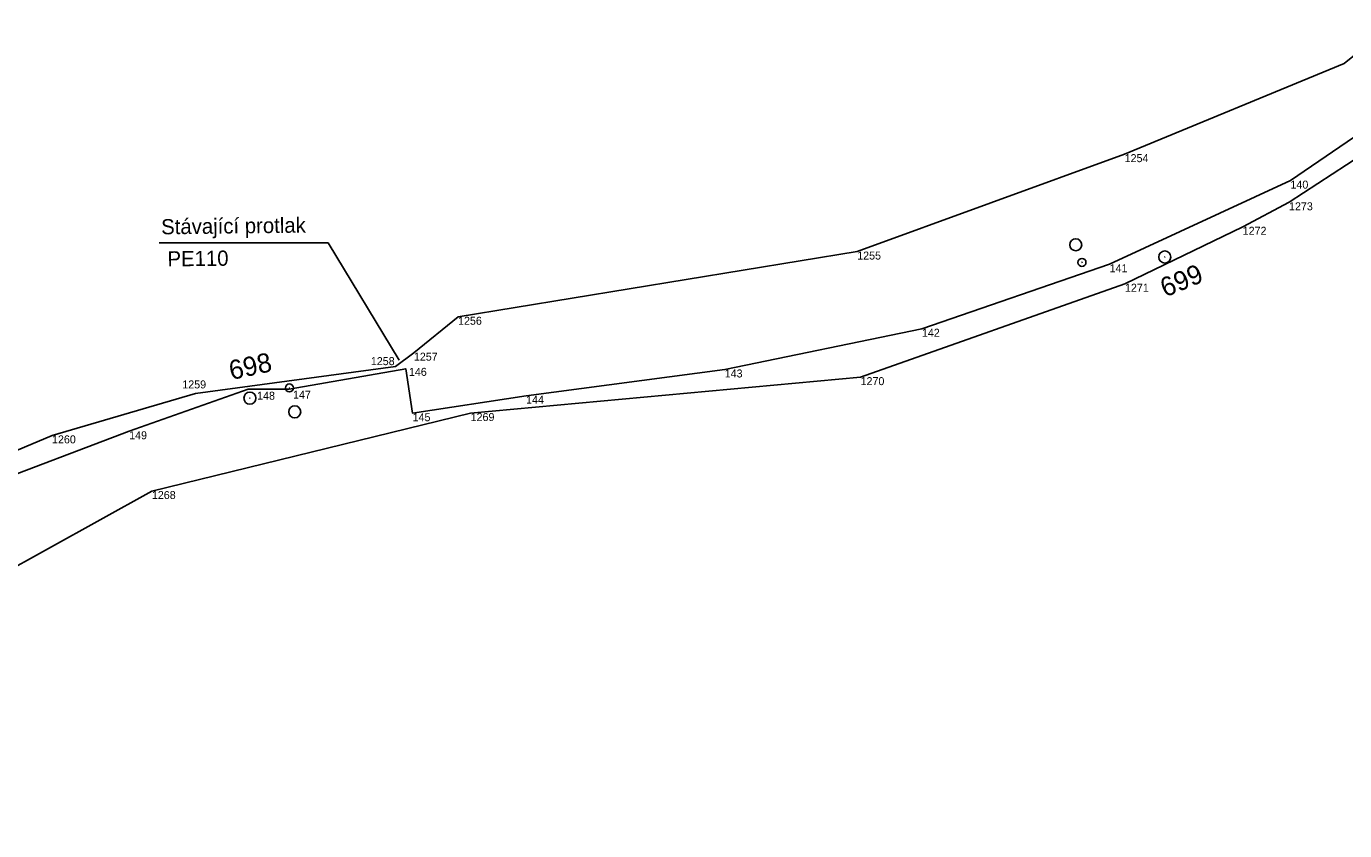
# Model space of a CAD drawing. Extents: x -679938 to -678300, y -1007495 to -1006487.
# Drawn here: x -679693.1 to -679528.4, y -1007298 to -1007197.5 of the extents above; entities that cross this region are included whole.
import ezdxf

# ---------------------------------------------------------------- set-up
doc = ezdxf.new("R2010")
doc.units = 0
for name, color, linetype in [('SSZT nové - lomové body', 7, 'Continuous'), ('SSZT_nové', 7, 'Continuous'), ('Stávající ŽBP', 7, 'Continuous'), ('SŽDC', 7, 'Continuous'), ('SŽDC - body', 7, 'Continuous'), ('Vrstva 7', 7, 'Continuous')]:
    doc.layers.add(name, color=color, linetype=linetype)

msp = doc.modelspace()

# ---------------------------------------------------------------- linework, layer by layer
at = {"layer": 'SSZT nové - lomové body'}
for p, q in [((-679535.13, -1007216.77), (-679535.13, -1007216.77)), ((-679557.73, -1007227.22), (-679557.73, -1007227.22)), ((-679581.18, -1007235.29), (-679581.18, -1007235.29)), ((-679645.68, -1007240.3), (-679645.68, -1007240.3)), ((-679605.83, -1007240.38), (-679605.83, -1007240.38)), ((-679665.36, -1007242.83), (-679665.36, -1007242.83)), ((-679660.24, -1007242.83), (-679660.24, -1007242.83)), ((-679630.65, -1007243.66), (-679630.65, -1007243.66)), ((-679644.83, -1007245.85), (-679644.83, -1007245.85)), ((-679680.25, -1007248.11), (-679680.25, -1007248.11))]:
    msp.add_line(p, q, dxfattribs=at)
at = {"layer": 'SSZT_nové'}
for q in [(-679676.5, -1007224.54), (-679646.52, -1007239.21)]:
    msp.add_line((-679655.39, -1007224.54), q, dxfattribs=at)
msp.add_lwpolyline([(-679506.94, -1007197.49), (-679535.13, -1007216.77), (-679557.73, -1007227.22), (-679581.18, -1007235.29), (-679605.83, -1007240.38), (-679630.65, -1007243.66), (-679644.83, -1007245.85), (-679645.68, -1007240.3), (-679660.24, -1007242.83), (-679665.36, -1007242.83), (-679680.25, -1007248.11), (-679698.48, -1007255.03), (-679713.76, -1007261.59), (-679729.9, -1007269.39), (-679734.01, -1007269.32), (-679749.53, -1007277.73), (-679746.78, -1007283.82), (-679755.45, -1007290.57), (-679757.54, -1007290.05), (-679765.84, -1007293.65), (-679771.62, -1007298.04)], dxfattribs=at)
at = {"layer": 'Stávající ŽBP'}
for p, q in [((-679550.89, -1007226.34), (-679550.8, -1007226.3)), ((-679665.21, -1007243.97), (-679665.11, -1007243.95))]:
    msp.add_line(p, q, dxfattribs=at)
for centre in [(-679550.84, -1007226.32), (-679665.16, -1007243.96)]:
    msp.add_circle(centre, 0.756, dxfattribs=at)
at = {"layer": 'SŽDC'}
for p, q in [((-679522.66, -1007197.48), (-679528.41, -1007202.14)), ((-679528.41, -1007202.14), (-679555.85, -1007213.46)), ((-679555.85, -1007213.46), (-679589.27, -1007225.64)), ((-679535.31, -1007219.48), (-679526.32, -1007213.61)), ((-679541.1, -1007222.54), (-679535.31, -1007219.48)), ((-679555.81, -1007229.66), (-679541.1, -1007222.54)), ((-679589.27, -1007225.64), (-679639.15, -1007233.79)), ((-679588.85, -1007241.34), (-679555.81, -1007229.66)), ((-679639.15, -1007233.79), (-679644.67, -1007238.28)), ((-679644.67, -1007238.28), (-679646.95, -1007240.02)), ((-679646.95, -1007240.02), (-679671.98, -1007243.39)), ((-679637.58, -1007245.83), (-679588.85, -1007241.34)), ((-679671.98, -1007243.39), (-679689.89, -1007248.62)), ((-679677.41, -1007255.58), (-679637.58, -1007245.83)), ((-679689.89, -1007248.62), (-679706.47, -1007255.7)), ((-679710.54, -1007274), (-679677.41, -1007255.58))]:
    msp.add_line(p, q, dxfattribs=at)
at = {"layer": 'SŽDC - body'}
for p, q in [((-679528.41, -1007202.14), (-679528.41, -1007202.14)), ((-679555.85, -1007213.46), (-679555.85, -1007213.46)), ((-679535.31, -1007219.48), (-679535.31, -1007219.48)), ((-679541.1, -1007222.54), (-679541.1, -1007222.54)), ((-679589.27, -1007225.64), (-679589.27, -1007225.64)), ((-679555.81, -1007229.66), (-679555.81, -1007229.66)), ((-679639.15, -1007233.79), (-679639.15, -1007233.79)), ((-679644.67, -1007238.28), (-679644.67, -1007238.28)), ((-679646.95, -1007240.02), (-679646.95, -1007240.02)), ((-679588.85, -1007241.34), (-679588.85, -1007241.34)), ((-679671.98, -1007243.39), (-679671.98, -1007243.39)), ((-679637.58, -1007245.83), (-679637.58, -1007245.83)), ((-679689.89, -1007248.62), (-679689.89, -1007248.62)), ((-679677.41, -1007255.58), (-679677.41, -1007255.58))]:
    msp.add_line(p, q, dxfattribs=at)
at = {"layer": 'Vrstva 7'}
for p, q in [((-679561.23, -1007227.02), (-679561.13, -1007226.98)), ((-679660.26, -1007242.7), (-679660.17, -1007242.68))]:
    msp.add_line(p, q, dxfattribs=at)
for centre, radius in [((-679561.96, -1007224.79), 0.75), ((-679561.18, -1007227), 0.5), ((-679660.22, -1007242.69), 0.5), ((-679659.56, -1007245.68), 0.75)]:
    msp.add_circle(centre, radius, dxfattribs=at)

# ---------------------------------------------------------------- texts
at = {"layer": 'SSZT nové - lomové body'}
for s, p in [('140', (-679535.13, -1007217.77)), ('141', (-679557.73, -1007228.22)), ('142', (-679581.18, -1007236.29)), ('146', (-679645.29, -1007241.18)), ('143', (-679605.83, -1007241.38)), ('148', (-679664.26, -1007244.16)), ('147', (-679659.77, -1007244.03)), ('144', (-679630.65, -1007244.66)), ('145', (-679644.83, -1007246.85)), ('149', (-679680.25, -1007249.11))]:
    msp.add_text(s, height=1, dxfattribs=at).set_placement(p)
at = {"layer": 'SSZT_nové'}
for s, p in [('Stávající protlak', (-679676.24, -1007223.49)), ('PE110', (-679675.45, -1007227.5))]:
    msp.add_text(s, height=1.9, rotation=0.7098, dxfattribs=at).set_placement(p)
at = {"layer": 'Stávající ŽBP'}
for s, rotation, p in [('699', 22.664, (-679550.77, -1007231.39)), ('698', 12.4023, (-679667.48, -1007241.71))]:
    msp.add_text(s, height=2.4, rotation=rotation, dxfattribs=at).set_placement(p)
at = {"layer": 'SŽDC - body'}
for s, p in [('1254', (-679555.85, -1007214.46)), ('1273', (-679535.31, -1007220.48)), ('1272', (-679541.1, -1007223.54)), ('1255', (-679589.27, -1007226.64)), ('1271', (-679555.81, -1007230.66)), ('1256', (-679639.15, -1007234.79)), ('1257', (-679644.67, -1007239.28)), ('1258', (-679650.05, -1007239.84)), ('1259', (-679673.61, -1007242.75)), ('1270', (-679588.85, -1007242.34)), ('1269', (-679637.58, -1007246.83)), ('1260', (-679689.89, -1007249.62)), ('1268', (-679677.41, -1007256.58))]:
    msp.add_text(s, height=1, dxfattribs=at).set_placement(p)

doc.saveas('drawing.dxf')
